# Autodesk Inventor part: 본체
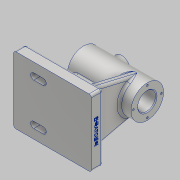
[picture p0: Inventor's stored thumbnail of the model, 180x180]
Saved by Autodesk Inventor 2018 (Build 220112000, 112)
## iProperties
Created: 2022-06
Part Number: 본체
Material: 알루미늄 6061
Document SubType Name: Modeling
Designer: home
Density: 2.7 g/cm^3
Appearance: 알루미늄 - 평지
Mass: 633.873 g
Surface Area: 513.431 cm^2
Volume: 234.768 cm^3
Author: home
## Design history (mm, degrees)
sketch "스케치1"
  geometry: L1 (50, -43)-(-50, -43); L2 (-50, -43)-(-50, 43); L3 (-50, 43)-(50, 43); L4 (50, 43)-(50, -43); 3 further points
  constraints: 8 end point, 2 midpoint, 2 parallel, 1 horizontal, 1 horizontal alignment, 1 perpendicular, 1 vertical alignment
  dimensions: "d0" = 100 distance of L1.start L1.end; "d1" = 86 distance of L1.end L2.end
extrude "돌출1" new body sketch "스케치1" distance "d2" = 15; taper "d3" = 0 deg
sketch "스케치2"
  geometry: L1 (-66.86, 72)-(81.788, 72); L2 (-50, 0)-(50, 0) reference; L3 (50, 83.5)-(50, 93); L4 (50, 93)-(-32, 93); L5 (-32, 93)-(-32, 86.5); L6 (50, 83.5)-(30, 83.5); L7 (30, 83.5)-(30, 86.5); L8 (30, 86.5)-(-32, 86.5); 2 further points
  constraints: 14 end point, 4 perpendicular, 2 horizontal, 1 midpoint, 1 vertical, 1 vertical alignment
  dimensions: "d4" = 72 distance between parallel lines of L2 L1; "d5" = 82 distance of L3.end L4.end; "d6" = 29 diameter of L8 L1; "d7" = 42 diameter of L4 L1; "d8" = 23 diameter of L6 L1; "d9" = 62 distance of L7.end L5.end
revolve "회전1" sketch "스케치2" stored, may be unused: angle "d10" = 90 deg
node "작업 평면1"
sketch "스케치4"
  geometry: L1 (8, 15)-(22.559, 76.814); L2 (78, 15)-(63.441, 76.814); L3 (86, 15)-(0, 15) reference; L4 (0, 0)-(0, 15) reference; L5 (86, 0)-(86, 15) reference; A1 r 21 centre (43, 72) between (22.559, 76.814) and (63.441, 76.814) reference; 1 further point
  constraints: 4 end point, 2 point on circle, 2 point on line, 2 tangent
  dimensions: "d15" = 8 distance from line of L4 L1.start; "d16" = 8 distance from line of L5 L2.start
extrude "돌출2" join sketch "스케치4" distance "d17" = 10; taper "d18" = 0 deg
sketch "스케치5"
  geometry: L1 (-35, 15)-(-21.897, 51); L2 (50, 15)-(-50, 15) reference; L3 (-32, 51)-(50, 51) reference; L4 (-50, 0)-(-50, 15) reference; 1 further point
  constraints: 2 end point, 2 point on line
  dimensions: "d19" = 15 distance from line of L4 L1.start; "d20" = 70 deg angle of L2 L1
feature "리브1" sketch "스케치5" dims "d21" = 1, "d22" = 10, "d23" = 0, "d24" = 0, "d25" = 1, "d26" = 1
sketch "스케치6"
  geometry: C1 r 21 at (0, 0) reference; 2 further points
  constraints: 1 vertical alignment
  dimensions: "d27" = 18 distance of C1.centre point (0, 18)
hole "구멍1" sketch "스케치6" at (0, 18) diameter "d28" = 2.459; stored, may be unused: countersink angle "d32" = 90 deg, drill point angle "d34" = 118 deg; dims "d29" = 8, "d30" = 4, "d31" = 2, "d33" = 10
sketch "스케치7"
  geometry: C1 r 1.23 at (0, 18) reference; C2 r 21 at (0, 0) reference; 2 further points
  constraints: 1 coincident
hole "구멍2" sketch "스케치7" at (0, 18) diameter "d38" = 2.459; stored, may be unused: countersink angle "d42" = 90 deg, drill point angle "d44" = 118 deg; dims "d39" = 8, "d40" = 4, "d41" = 2, "d43" = 10
sketch "스케치8"
  geometry: L1 (-24, 27)-(-12, 27); L2 (-24, 20)-(-12, 20); L3 (-12, 34)-(-24, 34); L4 (-50, -43)-(-50, 43) reference; L5 (-50, 43)-(50, 43) reference; A1 r 7 centre (-24, 27) between (-24, 34) and (-24, 20); A2 r 7 centre (-12, 27) between (-12, 20) and (-12, 34); 2 further points
  constraints: 8 end point, 4 point on circle, 4 tangent, 2 centre point, 1 horizontal, 1 midpoint, 1 parallel
  dimensions: "d48" = 12 distance of L1.start L1.end; "d49" = 26 distance from line of L4 L1.start; "d50" = 14 distance between parallel lines of L3 L2; "d51" = 16 distance between parallel lines of L5 L1
extrude "돌출3" join sketch "스케치8" distance "d52" = 3; taper "d53" = 0 deg
sketch "스케치9"
  geometry: L1 (-24, 20)-(-12, 20) reference; L2 (-12, 34)-(-24, 34) reference; L3 (-12, 23)-(-24, 23); L4 (-24, 31)-(-12, 31); A1 r 7 centre (-12, 27) between (-12, 20) and (-12, 34) reference; A2 r 7 centre (-24, 27) between (-24, 34) and (-24, 20) reference; A3 r 4 centre (-12, 27) between (-12, 23) and (-12, 31); A4 r 4 centre (-24, 27) between (-24, 31) and (-24, 23); 1 further point
  constraints: 4 end point, 4 point on circle, 2 centre point, 3 other
  dimensions: "d54" = 3 radial gap between concentric circles of A1 A3
extrude "돌출4" cut sketch "스케치9" extent not by distance; stored distance "d55" = 3; taper "d56" = 0 deg
fillet "모깎기1" dims "d57" = 3
node "작업 평면2"
sketch "스케치10"
  geometry: L1 (32, 21)-(32, -21) reference; C1 r 11 at (7, 0); 1 further point
  constraints: 1 centre point, 1 horizontal alignment
  dimensions: "d59" = 22 diameter of C1; "d60" = 25 distance from line of L1 C1.centre
extrude "돌출5" join sketch "스케치10" stored distance "d61" = 3; taper "d62" = 0 deg
sketch "스케치11"
  geometry: C1 r 11 at (0, 0) reference; 1 further point
hole "구멍3" sketch "스케치11" at (0, 0) diameter "d63" = 4.917; stored, may be unused: countersink angle "d67" = 90 deg, drill point angle "d69" = 118 deg; dims "d64" = 12, "d65" = 14, "d66" = 4, "d68" = 17.1
node "작업 평면3"
sketch "스케치12"
  geometry: 2 further points
  constraints: 1 horizontal alignment, 1 other
  dimensions: "d71" = 6 distance of point (0, 0) point (6, 0)
feature "엠보싱1" sketch "스케치12" dims "d0" = 100, "d1" = 86, "d9" = 62, "d72" = 0.5, "d73" = 0
fillet "모깎기2" dims "d74" = 3
fillet "모깎기3" dims "d75" = 3
chamfer "모따기1" distance "d76" = 1; stored, may be unused: second distance "d77" = 2, angle "d78" = 45 deg
fillet "모깎기4" dims "d79" = 3
fillet "모깎기5" dims "d80" = 3
fillet "모깎기6" dims "d81" = 1
node "솔리드1"
pattern_circular "원형 패턴1" dims angle "d36" = 360 deg
pattern_circular "원형 패턴2" dims angle "d46" = 360 deg
mirror "미러1"
node "투영된 루프1"
other parameters: "d14" = -15, "d58" = 96, "d70" = 72
